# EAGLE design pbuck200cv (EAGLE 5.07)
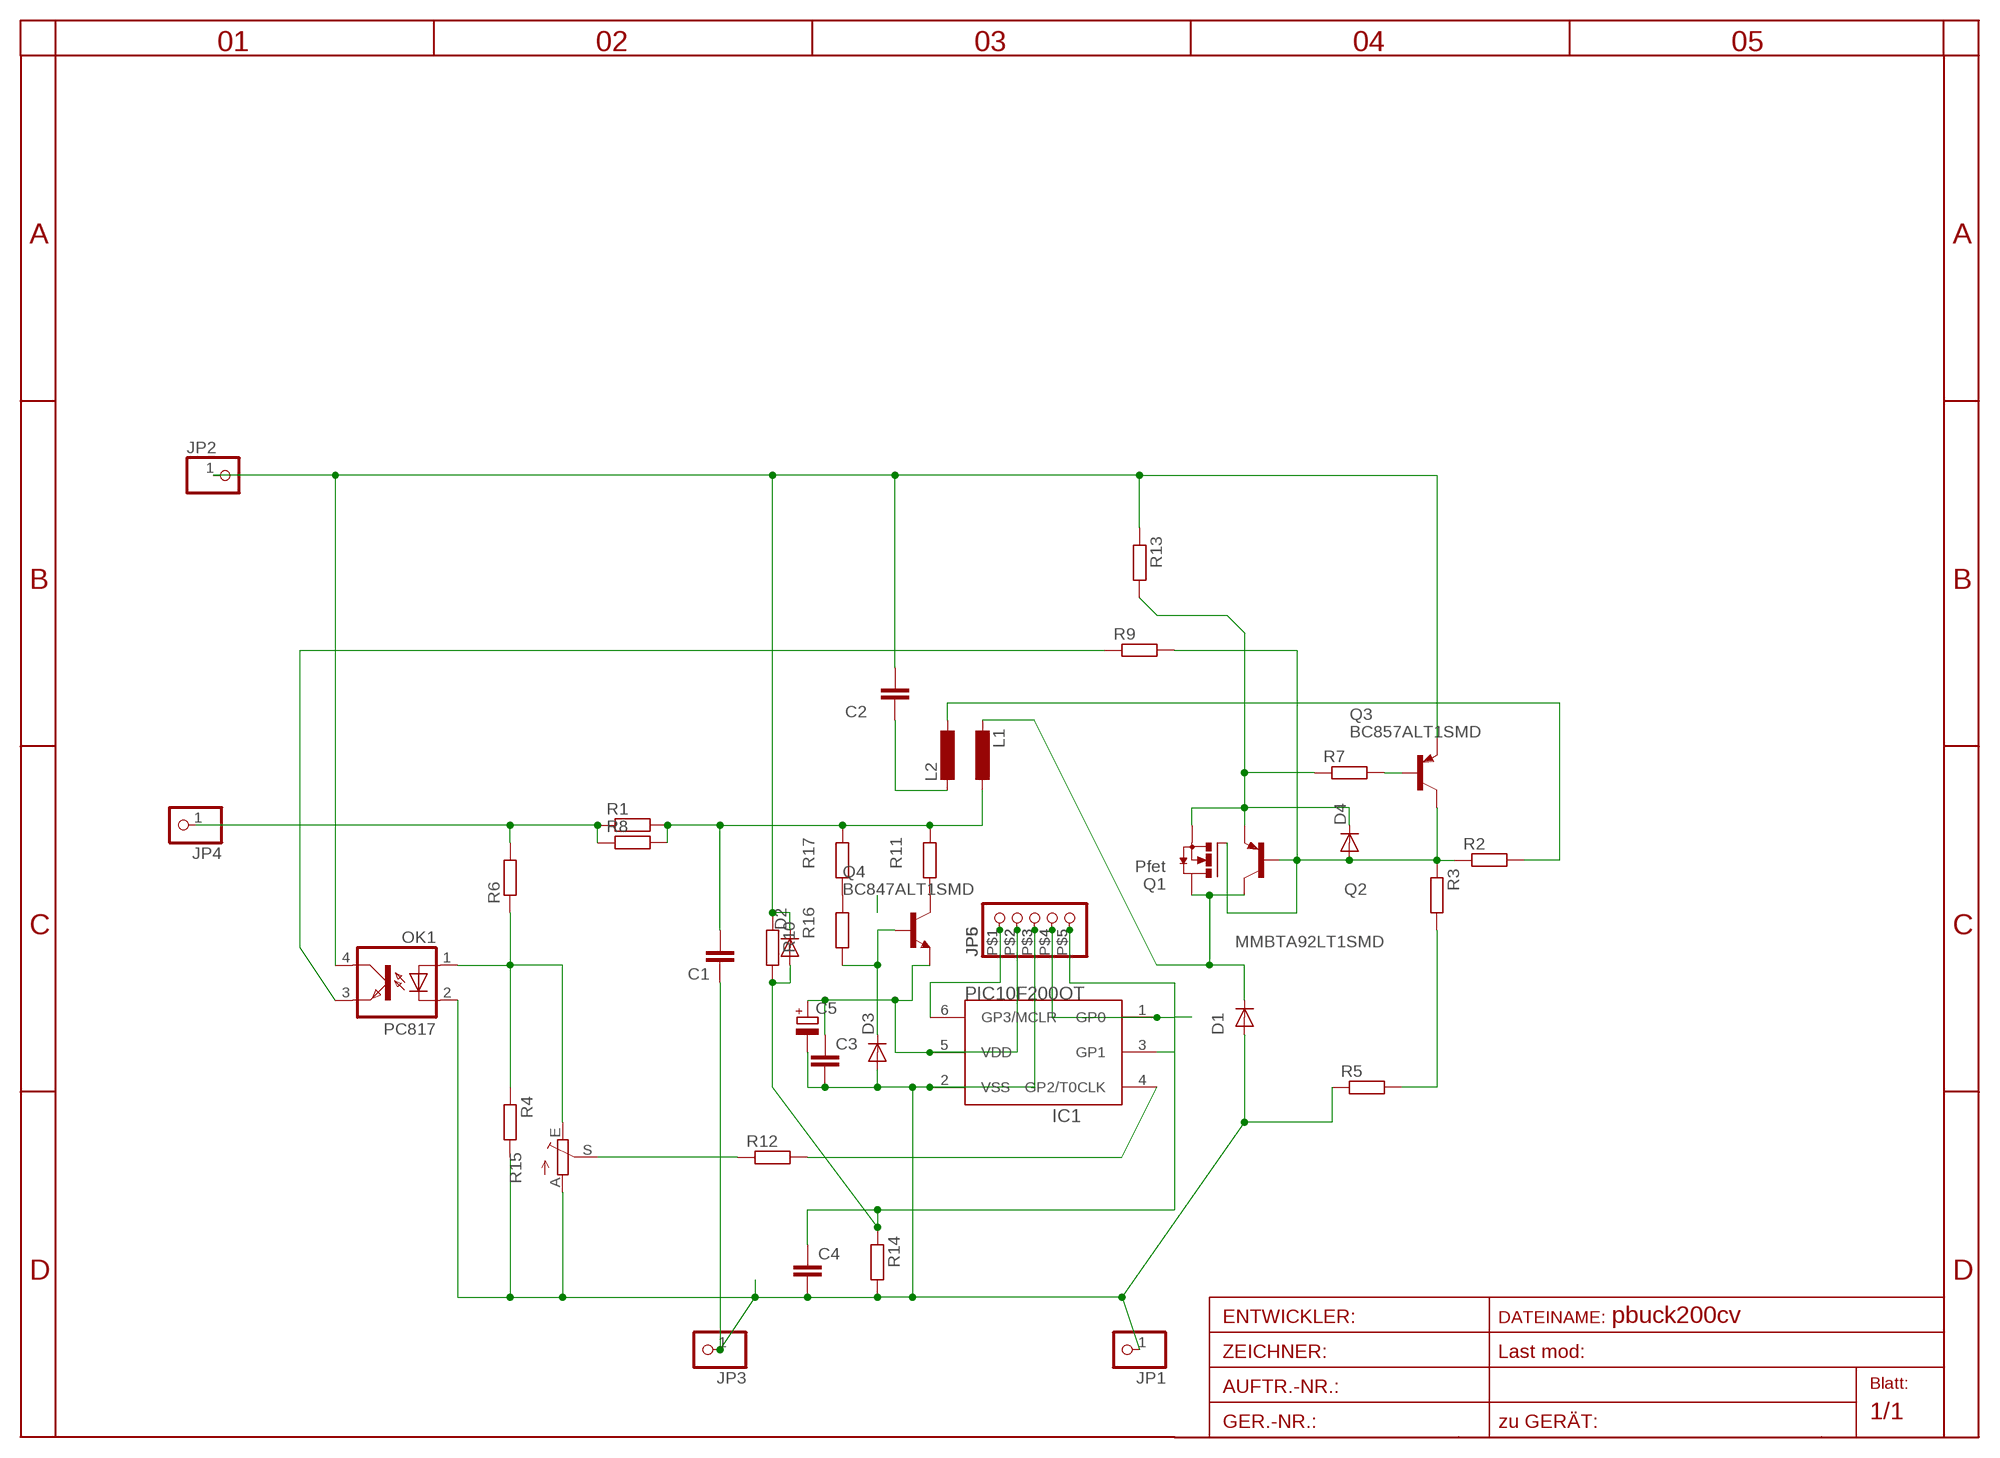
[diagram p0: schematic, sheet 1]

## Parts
C1  C-EU025-025X050  [C025-025X050]
C2  C-EUC0805  [C0805]
C3  C-EUC0805  [C0805]
C4  C-EUC0805  [C0805]
C5  CPOL-EUSMCA  [SMC_A]
D1  DIODE-SMC  [SMC]
D2  DIODE-MINIMELF  [MINIMELF]
D3  DIODE-MINIMELF  [MINIMELF]
D4  DIODE-MINIMELF  [MINIMELF]
IC1  PIC10F200OT  [SOT23-6]
JP1  PINHD-1X11MM6  [1X1MM8]
JP2  PINHD-1X11MM6  [1X1MM8]
JP3  PINHD-1X11MM6  [1X1MM8]
JP4  PINHD-1X11MM6  [1X1MM8]
JP5  PINHD-1X5  [1X05SMD]
JP6  PINHD-1X5/90  [1X05/90]
L1  L-EU0204/5  [0204/5]
L2  L-EU0207/10  [0207/10]
OK1  PC817  [DIL04]
Q1  Pfet  N-HEXFET_DPAK-  [TO252]
Q2  MMBTA92LT1SMD  [SOT23-BEC]
Q3  BC857ALT1SMD  [SOT23-BEC]
Q4  BC847ALT1SMD  [SOT23]
R1  R-EU_R2010  [R2010]
R2  R-EU_R0805  [R0805]
R3  R-EU_R1206  [R1206]
R4  R-EU_R0805  [R0805]
R5  R-EU_R1206  [R1206]
R6  R-EU_R0805  [R0805]
R7  R-EU_R1206  [R1206]
R8  R-EU_R2512  [R2512]
R9  R-EU_R0805  [R0805]
R10  R-EU_R0805  [R0805]
R11  R-EU_R1206  [R1206]
R12  R-EU_R0805  [R0805]
R13  R-EU_R1206  [R1206]
R14  R-EU_R0805  [R0805]
R15  TRIM_EU-CA6V  [CA6V]
R16  R-EU_R1206  [R1206]
R17  R-EU_R1206  [R1206]

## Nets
-: C1.1 C3.2 C4.2 C5.- D1.A D3.A IC1.2(VSS) JP1.1 JP3.1 JP5.P$3 JP6.3 OK1.2(C) R4.2 R5.1 R14.2 R15.A
B1C2: OK1.3(EMIT) R9.1
C1: D1.C L1.2 Q1.3(D) Q2.C
EB: D4.C Q1.2(S) Q2.E R7.1 R13.2
N$1: R3.2 R5.2
N$2: D4.A Q1.1(G) Q2.B Q3.C R2.1 R3.1 R9.2
N$3: Q3.B R7.2
N$4: L2.1 R2.2
N$5: Q4.3(C) R11.1
N$6: C2.1 L2.2
N$7: JP4.1 R1.1 R6.2 R8.1
N$8: R12.1 R15.S
N$9: IC1.4(GP2/T0CLK) R12.2
N$10: D3.C Q4.1(B) R16.1
N$12: C4.1 D2.A IC1.1(GP0) JP5.P$4 JP6.4 R10.2 R14.1
N$13: R16.2 R17.1
N$14: OK1.1(A) R4.1 R6.1 R15.E
N$15: C3.1 C5.+ IC1.5(VDD) JP5.P$2 JP6.2 Q4.2(E)
N$16: IC1.3(GP1) JP5.P$5 JP6.5
N$17: IC1.6(GP3/MCLR) JP5.P$1 JP6.1
OUT+: C1.2 L1.1 R1.2 R8.2 R11.2 R17.2
VPLUS: C2.2 D2.C JP2.1 OK1.4(COL) Q3.E R10.1 R13.1

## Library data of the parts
C1-C4 = rcl:C-EU: CAPACITOR, European symbol
C5 = rcl:CPOL-EU: POLARIZED CAPACITOR, European symbol
D1-D4 = diode:DIODE-: DIODE
IC1 = microchip-5:PIC10F20*: uPC nW 0,25/0,5k Program Flash memory
JP1-JP4 = pinhead:PINHD-1X1: PIN HEADER
JP5 JP6 = pinhead:PINHD-1X5: PIN HEADER
L1 L2 = rcl:L-EU: INDUCTOR, European symbol
OK1 = optocoupler:PC817: SHARP OPTO COUPLER
Q1 = transistor-power:N-HEXFET_?-*: HEXFET® Power MOSFET
Q2 = transistor-pnp:MMBTA92*: PNP Transistror
Q3 = transistor-pnp:BC857*: PNP Transistror
Q4 = transistor-npn:BC847*: NPN Transistor
R1-R14 R16 R17 = rcl:R-EU_: RESISTOR, European symbol
R15 = pot:TRIM_EU-: POTENTIOMETER

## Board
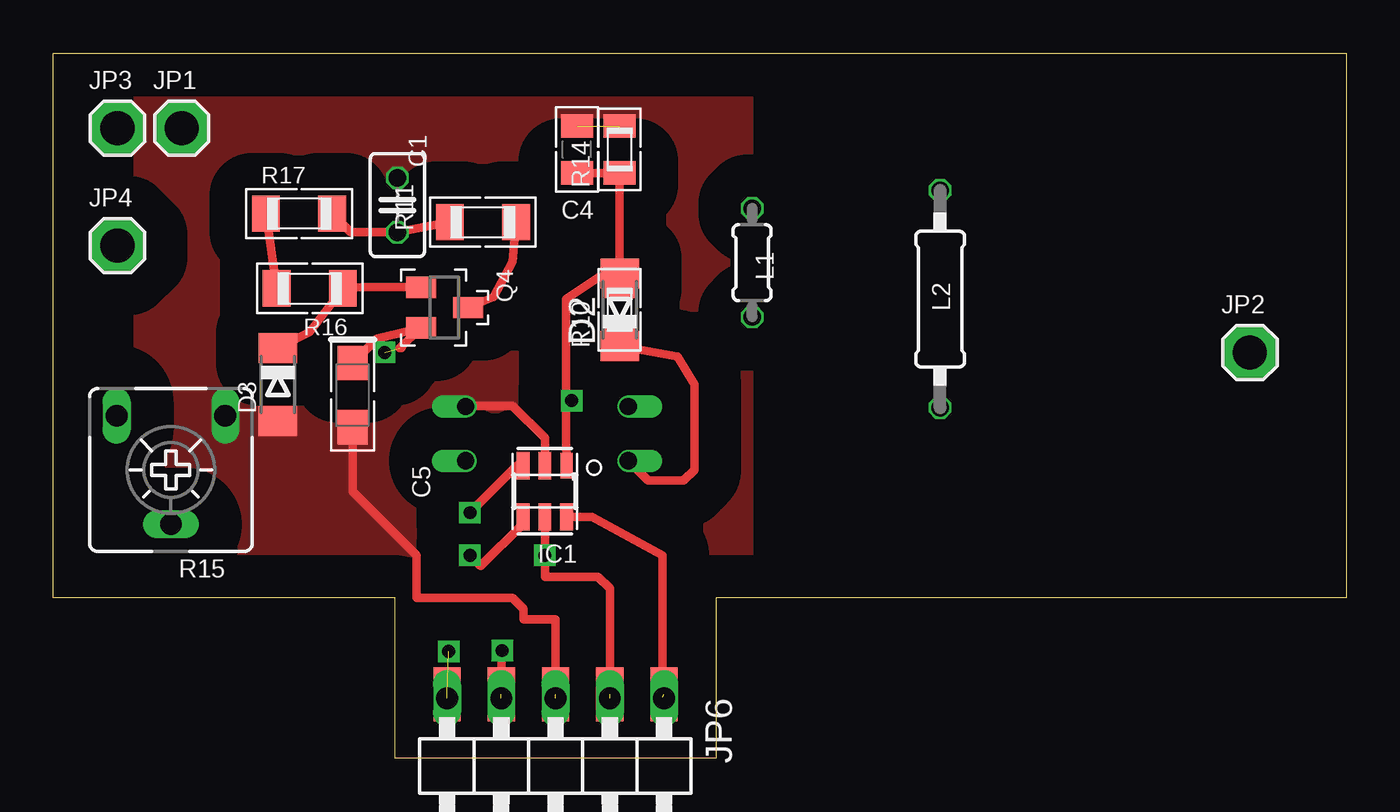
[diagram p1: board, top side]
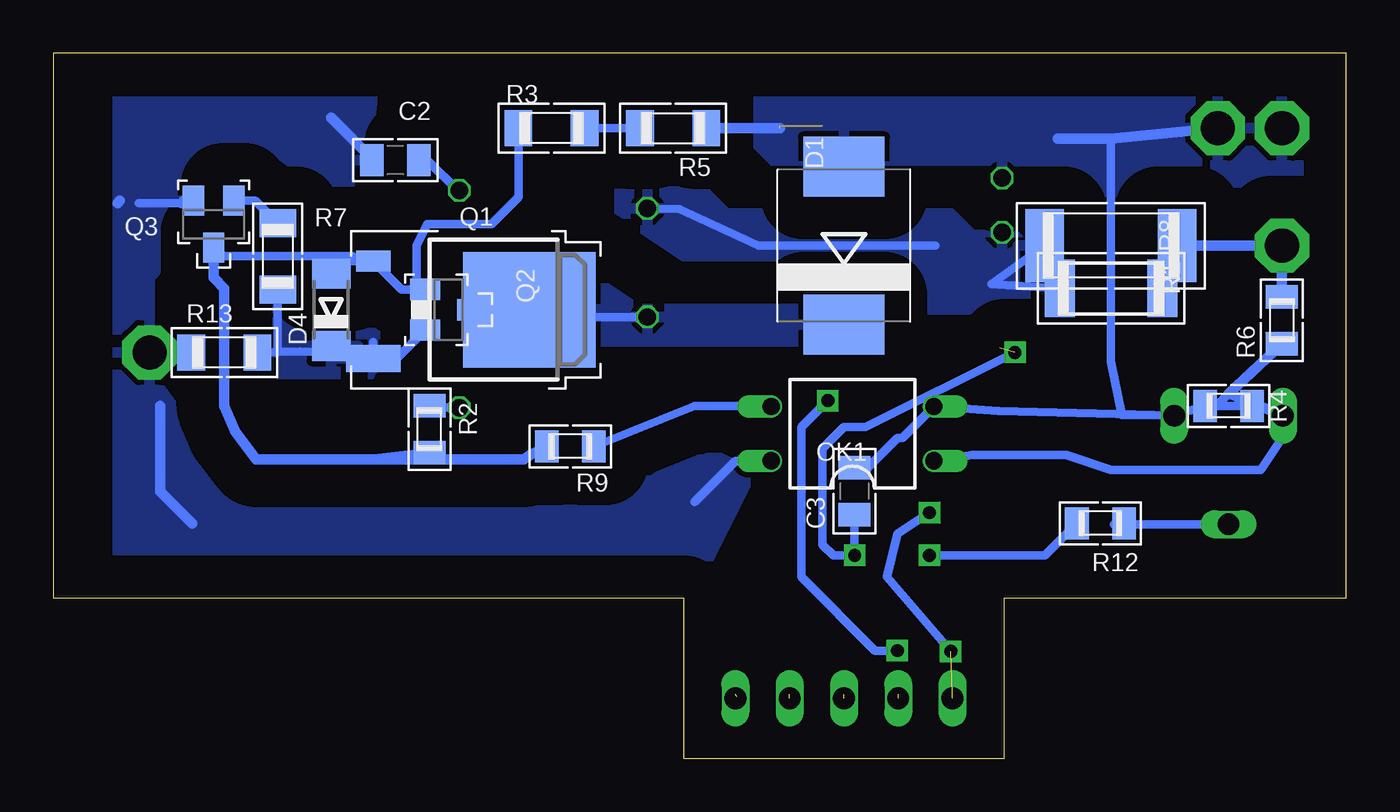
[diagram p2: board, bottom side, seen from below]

Size 60.5 x 33 mm. Coordinates in mm from the lower left corner, seen from the top.
Outline: 0,33 60.5,33 60.5,7.5 31,7.5 31,0 16,0 16,7.5 0,7.5 0,33
Copper layers (1*16): Top 0.035mm / dielectric 1.5mm / Bottom 0.035mm
Design rules "default *": minimum track width 10mil, minimum drill 20mil, track to track 8mil, track to pad 8mil, pad to pad 8mil, via to via 8mil, smd to smd 8mil, copper to edge 40mil, drill to drill 8mil, minimum pad ring 1mil, minimum via ring 8mil, stop-mask expansion 4mil, vias tented up to drill 0mil, thermal gap 10mil

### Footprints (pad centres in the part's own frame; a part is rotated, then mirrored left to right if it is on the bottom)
C025-025X050 = drill 0.813 octagon: 1 -1.27,0; 2 1.27,0
C0805 = smd 1.1 x 1.5: 1 -1.1,0; 2 1.1,0
SMC_A = smd 1.6 x 1.4: + -1.5,0; - 1.5,0
SMC = smd 2.8 x 3.8: A 3.7,0; C -3.7,0
MINIMELF = smd 1.4 x 1.8: A 1.7,0; C -1.7,0
SOT23-6 = smd 0.55 x 1.2: 1 -1.016,-1.2 | smd 0.6 x 1.27: 2 0,-1.2; 3 1.016,-1.2; 4 1.016,1.2; 5 0,1.2; 6 -1.016,1.2
1X1MM8 = drill 1.6 pad 2.54 octagon: 1 0,0
1X05SMD = smd 1.27 x 2.54: P$1 -5.08,0; P$2 -2.54,0; P$3 0,0; P$4 2.54,0; P$5 5.08,0
1X05/90 = drill 1.016 long: 1 -5.08,-3.81; 2 -2.54,-3.81; 3 0,-3.81; 4 2.54,-3.81; 5 5.08,-3.81
0204/5 = drill 0.813 octagon: 1 -2.54,0; 2 2.54,0
0207/10 = drill 0.813 octagon: 1 -5.08,0; 2 5.08,0
DIL04 = drill 0.813 offset: 1 -1.27,-3.81; 2 1.27,-3.81; 3 1.27,3.81; 4 -1.27,3.81
TO252 = smd 1 x 1.6: 1 -2.28,-3.53 | smd 1.27 x 2.54: 2 2.28,-3.53 | smd 5.4 x 6.2: 3 0,3.77
SOT23-BEC = smd 1 x 1.4: B -0.95,-1.1; C 0,1.1; E 0.95,-1.1
SOT23 = smd 1 x 1.4: 1 -0.95,-1.1; 2 0.95,-1.1; 3 0,1.1
R2010 = smd 1.4 x 2.7: 1 -2.4,0; 2 2.4,0
R0805 = smd 1.1 x 1.5: 1 -1.1,0; 2 1.1,0
R1206 = smd 1.3 x 1.7: 1 -1.55,0; 2 1.55,0
R2512 = smd 1.8 x 3.4: 1 -3.1,0; 2 3.1,0
CA6V = drill 1.016 long: A -2.54,-2.54; E 2.54,-2.54; S 0,2.54

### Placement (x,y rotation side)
C1  16.1,25.9 270 top
C2  44.5,28 180 bottom
C3  23,12.5 90 bottom
C4  24.5,28.5 90 top
C5  14,17 270 top
D1  23.5,24 90 bottom
D2  26.5,21 90 top
D3  10.5,17.5 270 top
D4  47.5,21 90 bottom
IC1  23,12.5 180 top
JP1  6,29.5 0 top
JP2  56,19 0 top
JP3  3,29.5 0 top
JP4  3,24 0 top
JP5  23.5,3 180 top
JP6  23.5,-1 180 top
L1  32.7,23.2 270 top
L2  41.5,21.5 90 top
OK1  23.1,15.2 90 bottom
Q1  42,21 270 bottom
Q2  42,21 270 bottom
Q3  53,25 180 bottom
Q4  18.3,21.1 270 top
R1  11,22 180 bottom
R2  42.9,15.4 90 bottom
R3  37.19,29.5 0 bottom
R4  5.5,16.5 180 bottom
R5  31.5,29.5 180 bottom
R6  3,20.5 90 bottom
R7  50,23.5 90 bottom
R8  11,24 180 bottom
R9  36.3,14.6 180 bottom
R10  26.5,21 90 top
R11  20.1,25.1 180 top
R12  11.5,11 180 bottom
R13  52.5,19 0 bottom
R14  26.5,28.5 90 top
R15  5.5,13.5 180 top
R16  12,22 180 top
R17  11.5,25.5 0 top

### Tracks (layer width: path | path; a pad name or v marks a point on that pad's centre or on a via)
-  (3 unrouted)
  Top 0.406: IC1.2 23,15 21.5,16.5 19.32,16.5 OK1.2 | JP5.P$3 23.5,6.5 22,6.5 22,7 21.5,7.5 17,7.5 17,9.5 14,12.5 C5.-
  Bottom 0.406: R15.A 10.5,16.08 11,18.58 11,29 | R4.2 8.06,16.04 R15.A | R15.A 16.27,16.27 OK1.2 20.76,15 21,15 22.4,13.6 C3.2
  Bottom 0.5: 13.5,29 11,29 JP1.1 | 26.5,29.5 R5.1
  pour Bottom (isolate 2, rank 2): 1.5,31 27.5,31 27.5,26.5 1.5,26.5
  pour Top (isolate 2, rank 2, no thermals): 4,32 32.5,31.5 32.5,8.5 4,8.5
B1C2
  Bottom 0.406: R9.1 30.5,16.5 28.08,16.5 28.05,16.47 OK1.3
C1
  Bottom 0.406: L1.2 37.89,20.66 Q1.3 Q2.C
  pour Bottom (isolate 2, rank 2): 25,23 37,23.5 37,19.5 25,19.5
EB
  Bottom 0.406: 50,19.02 48.95,19.05 47.5,19 45.81,19 Q1.2 | 50,19.02 R13.2 | Q1.2 44.43,18.72 Q2.E | Q1.2 45.53,19.48 | R7.1 50,19.02
  pour Bottom (isolate 2, rank 2): 42.5,20.5 45.5,20.5 47,22 51,22 51,18 43.5,18 42.5,18.5
N$1
  Bottom 0.406: R5.2 R3.2
N$2
  Bottom 0.406: 46.28,23.28 Q1.1 44.2,21.95 Q2.B 43.5,22.35 43.5,24 43,25 40,25 38.74,26.26 R3.1 | 46.28,23.28 46.5,23.5 52.6,23.5 Q3.C | D4.A 46.92,23.28 46.28,23.28
  Bottom 0.5: R9.2 38.2,14.2 38.5,14 45.5,14 | 45.5,14 51,14 52,15.3 52.5,16.5 52.5,22 53,22.5 Q3.C | 45.5,14 R2.1
N$3
  Bottom 0.406: R7.2 51.05,26.1 Q3.B
N$4
  Bottom 0.406: L2.1 42.38,16.42 R2.2
N$5
  Top 0.406: Q4.3 20.6,21.6 21.5,23.25 R11.1
N$6
  Bottom 0.406: L2.2 41.5,26.5 43,28 C2.1
N$7
  Bottom 0.5: R6.2 JP4.1 R8.1 7.9,23.2 R1.1
N$8
  Bottom 0.406: R15.S 10.86,10.96 R12.1
N$9  (via drill 0.6)
  Top 0.406: IC1.4 21.98,10.98 20,9 v19.5,9.5
  Bottom 0.406: v19.5,9.5 14.1,9.5 R12.2
N$10
  Top 0.406: D3.C 12,19.95 R16.1 14.5,22.05 Q4.1
N$12  (via drill 0.6)  (1 unrouted)
  Top 0.406: JP5.P$4 v21,5.04 | C4.1 R14.1 D2.A 26.3,22.5 | IC1.1 24,15.1 24,16.5 | 24,16.5 24,21.5 25.5,22.5 26.3,22.5 | 24.5,17 v24.25,16.75 24,16.5 | 26.3,22.5 26.3,22.3 R10.2
  Bottom 0.406: v21,5.04 22.04,5.04 25.5,8.5 25.5,15.5 v24.25,16.75
N$13
  Top 0.406: R16.2 R17.1
N$14
  Bottom 0.406: OK1.1 17.52,14.2 13.1,14.2 11,13.5 4,13.5 2.96,15.04 R15.E | 5.5,17.08 6.08,16.5 R4.1
  Bottom 0.5: R6.1 5.5,17.08 R15.E
N$15  (via drill 0.6)  (2 unrouted)
  Top 0.406: JP5.P$2 26.04,7.96 25.5,8.5 23,8.5 v23,9.5 IC1.5 | C5.+ 15.15,19.65 Q4.2 16.2,19.2 16.3,19.2
  Bottom 0.406: C3.1 v23,9.5 24,9.5 24.5,10 24.5,14.5 23.5,15.5 22.5,15.5 v15.5,19
N$16  (via drill 0.6)  (2 unrouted)
  Top 0.406: IC1.3 21.7,13.7 v19.5,11.5
  Bottom 0.406: v19.5,11.5 21,10.5 21.5,8.5 v18.5,5
N$17  (1 unrouted)
  Top 0.406: IC1.6 25.2,11.3 28.5,9.5 28.5,2.89 JP6.1
OUT+
  Top 0.406: R11.2 C1.2 13.92,24.63 R17.2
  Bottom 0.406: L1.1 31.2,25.7 27.5,24 19.23,24 | R1.2 16.6,22.2 R8.2
  pour Bottom (isolate 2): 30,27 34,27 34,25.5 31,23.5 22,23.5 19.5,21 15.5,21 15,21.5 15,24 15.5,24.5 17.5,24.5 18.5,25.5 29,25.5 30,26.5
VPLUS
  Top 0.406: R10.1 D2.C 29.2,18.8 30,17.5 30,13.5 29.5,13 27.84,13 OK1.4
  Bottom 0.406: 54.5,26 56.5,26 | OK1.4 28.57,13.93 30.5,12
  Bottom 0.5: 54,11 55.5,12.5 55.5,16.5 | 57,19 57,18.5 | 57.5,26 57.4,26.1 | JP2.1 56.5,19.5 57,19 | C2.2 45.6,28.1 47.5,30 | R13.1 JP2.1 | JP2.1 57,19 | Q3.E 54.4,26.1 54.5,26
  pour Bottom (isolate 2, rank 2): 45.5,31.5 57.5,31.5 57.5,8 30.5,8 28,13 27,15.5 30,14 31,14 32.5,13 38,13 52,12.5 56,18 56,22.5 52.5,26.5 52,27 46,27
